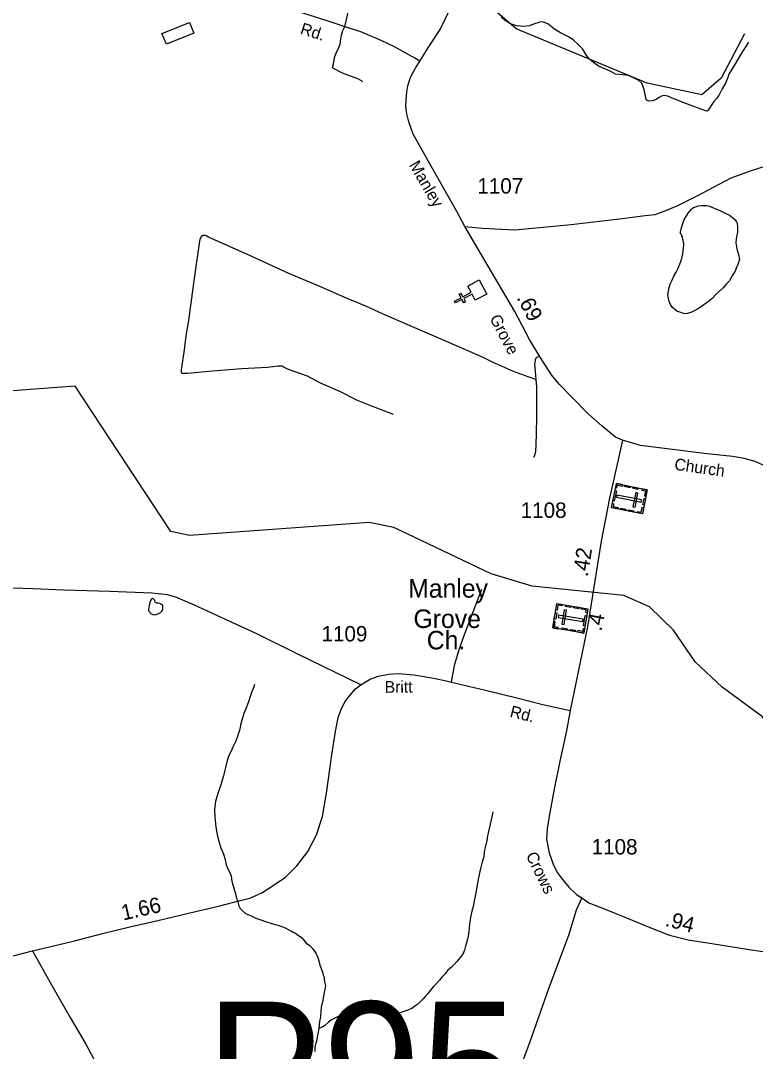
# Model space of a CAD drawing. Extents: x 2206922 to 2357709, y 510027 to 673830.
# Drawn here: x 2230004 to 2235957, y 541278 to 549625 of the extents above; entities that cross this region are included whole.
import ezdxf

# ---------------------------------------------------------------- set-up
doc = ezdxf.new("R2010")
doc.units = 0
for name, color, linetype in [('Exist Cultural Cemetery CELL', 7, 'Continuous'), ('Exist Cultural Cemetery Label', 7, 'Continuous'), ('Exist Cultural Church CELL', 7, 'Continuous'), ('Exist Hydrographic Creek Single Shore', 7, 'Continuous'), ('Exist Hydrographic Misc Water Feature', 7, 'Continuous'), ('Exist Road Non-System Type 51', 7, 'Continuous'), ('Exist Road Secondary Mileage Hundredths English Label', 7, 'Continuous'), ('Exist Road Secondary Structure Pipe Number Label', 7, 'Continuous'), ('Exist Road Secondary Type 51 Attributed', 7, 'Continuous'), ('Exist Road Secondary Type 51 Label', 7, 'Continuous'), ('Exist Road Secondary Type 51 Number Label', 7, 'Continuous')]:
    doc.layers.add(name, color=color, linetype=linetype)

msp = doc.modelspace()

# ---------------------------------------------------------------- linework, layer by layer
at = {"layer": 'Exist Cultural Cemetery CELL'}
for points in [[(2235080.5, 545825.9), (2235041.3, 545630.7), (2234791.6, 545681), (2234830.9, 545876.1)], [(2234830.8, 545817.5), (2234814.1, 545734.4), (2234802.9, 545736.6), (2234819.6, 545819.8)], [(2234824.4, 545843.7), (2234835.7, 545841.4), (2234840, 545863), (2234879.6, 545855), (2234881.8, 545865.9), (2234831, 545876.2)], [(2234899.5, 545862.4), (2234941.9, 545853.8), (2234939.7, 545842.7), (2234897.2, 545851.2)], [(2234965.4, 545849.1), (2235007.8, 545840.6), (2235005.6, 545829.4), (2234963.1, 545837.9)], [(2235005.8, 545799.3), (2234987.5, 545803), (2234964.2, 545687.6), (2234982.5, 545683.9)], [(2235038.1, 545834.5), (2235035.8, 545823.3), (2235067.4, 545817), (2235059.4, 545777.2), (2235070.3, 545775), (2235080.5, 545825.9)], [(2234798.2, 545713.4), (2234809.4, 545711.2), (2234805.1, 545689.6), (2234844.7, 545681.6), (2234842.5, 545670.7), (2234791.6, 545681)], [(2235030.3, 545724.8), (2235034, 545743.1), (2234835.2, 545783.1), (2234831.5, 545764.8)], [(2235065.9, 545753.3), (2235055.7, 545702.5), (2235044.5, 545704.7), (2235054.7, 545755.5)], [(2234864.7, 545677.9), (2234907.2, 545669.3), (2234904.9, 545658.1), (2234862.5, 545666.7)], [(2234929.3, 545664.8), (2234971.8, 545656.3), (2234969.6, 545645.1), (2234927.1, 545653.7)], [(2234998.7, 545639.2), (2235001, 545650.3), (2235032.5, 545644), (2235040.5, 545683.8), (2235051.4, 545681.6), (2235041.2, 545630.7)], [(2234315.7, 544707.8), (2234348.4, 544904.1), (2234599.6, 544862.3), (2234566.9, 544665.9)], [(2234391.2, 544897.1), (2234389.3, 544885.9), (2234357.6, 544891.2), (2234350.9, 544851.2), (2234340, 544853), (2234348.5, 544904.2)], [(2234461.4, 544873.8), (2234418.7, 544880.9), (2234420.6, 544892.2), (2234463.3, 544885)], [(2234526.4, 544863), (2234483.7, 544870.1), (2234485.6, 544881.3), (2234528.3, 544874.2)], [(2234327.9, 544780.8), (2234336.4, 544831.9), (2234347.7, 544830.1), (2234339.2, 544778.9)], [(2234362.5, 544810.5), (2234359.5, 544792.1), (2234559.5, 544758.7), (2234562.6, 544777.2)], [(2234389.6, 544736.8), (2234408, 544733.8), (2234427.3, 544849.9), (2234408.9, 544853)], [(2234594.2, 544829.6), (2234582.8, 544831.5), (2234586.4, 544853.2), (2234546.6, 544859.9), (2234548.4, 544870.8), (2234599.6, 544862.3)], [(2234565, 544724.5), (2234578.9, 544808.2), (2234590.2, 544806.3), (2234576.3, 544722.6)], [(2234358.5, 544700.6), (2234360.3, 544711.8), (2234328.6, 544717.1), (2234335.2, 544757.1), (2234324.2, 544758.9), (2234315.7, 544707.8)], [(2234431.6, 544688.4), (2234388.9, 544695.5), (2234390.7, 544706.8), (2234433.5, 544699.7)], [(2234497.9, 544677.4), (2234455.2, 544684.5), (2234457, 544695.7), (2234499.8, 544688.6)], [(2234572.3, 544698.6), (2234560.9, 544700.4), (2234557.3, 544678.7), (2234517.5, 544685.4), (2234515.6, 544674.4), (2234566.8, 544665.9)]]:
    msp.add_lwpolyline(points, close=True, dxfattribs=at)
at = {"layer": 'Exist Cultural Church CELL'}
msp.add_lwpolyline([(2233688, 547360.7), (2233661, 547410.8), (2233593.9, 547374.9), (2233609, 547346.6), (2233594.9, 547339.1), (2233579.8, 547367.3), (2233526.8, 547338.9), (2233519.2, 547353), (2233572.2, 547381.4), (2233557.1, 547409.6), (2233571.2, 547417.2), (2233586.3, 547389), (2233653.4, 547424.9), (2233626.3, 547475.8), (2233720.1, 547526.1), (2233781.8, 547410.9)], close=True, dxfattribs=at)
at = {"layer": 'Exist Hydrographic Creek Single Shore'}
for points in [[(2235868.2, 549517.9), (2235679.4, 549157.6), (2235522.3, 549023.1), (2235080.2, 549117.2), (2234018.3, 549558.5), (2233808.3, 549739.8)], [(2238109.5, 540472.8), (2238163.4, 541996.9), (2238052.4, 542314), (2237866.5, 542603.1), (2237682.3, 542777.3), (2237121.3, 543106.8), (2236403.4, 543367.2), (2236227.3, 543498.7), (2236107.3, 543855.3), (2236015.3, 543988.4), (2235688.4, 544227.9), (2235469.4, 544432.3), (2235292.2, 544688.5), (2235099.3, 544879.3), (2234890.3, 544968.8), (2234148.3, 545046.1), (2233815.3, 545144.7), (2233028.3, 545521.3), (2232828.3, 545561.4), (2231371.2, 545456.3), (2231221.3, 545488.8), (2230446.2, 546665.6), (2228706.2, 546536.6), (2228754.2, 545669.8)]]:
    msp.add_lwpolyline(points, dxfattribs=at)
at = {"layer": 'Exist Hydrographic Misc Water Feature'}
for points in [[(2232774.8, 549129.6), (2232765.2, 549137.5), (2232735, 549153.4), (2232612.4, 549200.3), (2232544.3, 549233.7), (2232538.2, 549237.5), (2232534.3, 549241.7), (2232532.2, 549245.6), (2232534.3, 549255.5), (2232538.2, 549275.6), (2232549.5, 549333.5), (2232567.1, 549375.8), (2232578.8, 549400), (2232592.5, 549434), (2232594.4, 549458.1), (2232604, 549508.2), (2232615.5, 549546.1), (2232631.5, 549576.2), (2232664.3, 549714.4)], [(2235901.2, 549449.2), (2235839.5, 549354.6), (2235792.6, 549276.2), (2235741.5, 549191.8), (2235733.3, 549163.8), (2235717.7, 549123.6), (2235688.2, 549071.3), (2235660.5, 549019.2), (2235640.6, 548995), (2235619.3, 548971), (2235575.6, 548900.5), (2235565.8, 548892.7), (2235551.6, 548894.4), (2235517.4, 548908.1), (2235429.6, 548939.6), (2235337.1, 548976.7), (2235277.3, 549000.3), (2235246.7, 549013.8), (2235214.7, 549017.4), (2235197.1, 549013.6), (2235177, 549003.3), (2235147.3, 548983), (2235119.6, 548974.6), (2235095.4, 548972.6), (2235081, 548978.4), (2235073, 548986.5), (2235054.6, 549066.3), (2235036.3, 549118.2), (2235012.3, 549140), (2234979.5, 549157.5), (2234929.7, 549179.3), (2234879.9, 549184.7), (2234823.5, 549192.4), (2234785.4, 549214), (2234737.6, 549235.4), (2234687.1, 549257.2), (2234644.9, 549286.7), (2234612.7, 549312.6), (2234592.6, 549340.4), (2234556.3, 549397.8), (2234518, 549435.6), (2234483.3, 549465.6), (2234447.2, 549491.2), (2234378.9, 549524.7), (2234330.5, 549556.3), (2234302.7, 549577.9), (2234276.6, 549597.7), (2234240.7, 549611.2), (2234222.7, 549615.1), (2234202.4, 549610.9), (2234166.3, 549598.9), (2234124.9, 549582.4), (2234081, 549578.1), (2234020.7, 549581.6), (2233972.7, 549599.4), (2233928.4, 549624.7), (2233898.1, 549652.4)], [(2231149, 549520), (2231371.8, 549610.1), (2231406.5, 549522.2), (2231185.3, 549434.6), (2231149, 549520)], [(2235811.4, 547953), (2235813.3, 547910.9), (2235799.9, 547859), (2235798.1, 547824.8), (2235802.6, 547792.9), (2235809, 547767.2), (2235819.2, 547731.2), (2235827.6, 547693.4), (2235815.7, 547649), (2235802, 547621.1), (2235792.6, 547597), (2235768.8, 547558.8), (2235746.8, 547518.7), (2235720.8, 547490.6), (2235695.4, 547462.4), (2235669.7, 547436.3), (2235639.8, 547409.9), (2235606, 547375.7), (2235588.5, 547359.3), (2235558.4, 547337.1), (2235520.9, 547311.1), (2235488.7, 547288.8), (2235465.1, 547276.5), (2235433.3, 547262.3), (2235405.2, 547253.9), (2235387.4, 547251.8), (2235367.1, 547255.6), (2235343.5, 547263.7), (2235321.2, 547273.5), (2235303.1, 547285.1), (2235284.9, 547302.9), (2235270.9, 547320.8), (2235258.4, 547350.7), (2235252.3, 547374.7), (2235248.4, 547404.5), (2235252.1, 547434.8), (2235257.6, 547462.7), (2235267.4, 547490.9), (2235279.1, 547518.6), (2235296.8, 547554.9), (2235314.8, 547589.1), (2235328.3, 547615.1), (2235344.1, 547653.3), (2235357.9, 547689.3), (2235369.1, 547737.4), (2235374.7, 547783.7), (2235376.9, 547801.6), (2235376.7, 547815.4), (2235374.5, 547833.6), (2235370.2, 547853.3), (2235366.3, 547873.3), (2235362.2, 547881.3), (2235360.1, 547885.2), (2235358.3, 547891.2), (2235353.8, 547895.5), (2235350.1, 547903.4), (2235347.8, 547907.4), (2235350.1, 547913.1), (2235357.7, 547949.3), (2235369.3, 547983.2), (2235381.2, 548013.4), (2235395, 548037.7), (2235412.8, 548065.8), (2235438, 548097.7), (2235444.2, 548104.1), (2235456.3, 548112), (2235472.1, 548118.1), (2235496.1, 548124.2), (2235520.3, 548128.7), (2235546.1, 548128.8), (2235564.1, 548126.9), (2235584, 548121.1), (2235623.8, 548105.3), (2235668.1, 548087.8), (2235700.3, 548071.9), (2235746.6, 548048.3), (2235773.1, 548028.5), (2235792.6, 548011), (2235805.1, 547996.9), (2235809.2, 547985), (2235811.4, 547953)], [(2231060.2, 544936.1), (2231058.3, 544930.3), (2231052, 544917.9), (2231050.3, 544908), (2231046.4, 544889.9), (2231042.5, 544873.9), (2231040.7, 544857.9), (2231040.9, 544848.2), (2231044.8, 544841.9), (2231048.9, 544836), (2231053.2, 544830.2), (2231058.9, 544824.4), (2231065.1, 544820.2), (2231074.9, 544816.3), (2231087, 544814.5), (2231101, 544816.4), (2231109, 544818.5), (2231117, 544822.6), (2231127, 544826.7), (2231136.9, 544832.9), (2231148.8, 544842.9), (2231154.7, 544850.9), (2231156.5, 544857.1), (2231156.5, 544868.9), (2231156.5, 544877), (2231156.5, 544885.1), (2231156.5, 544889.2), (2231154.5, 544892.7), (2231146.3, 544896.8), (2231140.1, 544898.9), (2231136.2, 544902.7), (2231132.1, 544904.6), (2231120.3, 544906.8), (2231114.3, 544906.5), (2231110, 544906.7), (2231104.5, 544908.4), (2231098.3, 544912.5), (2231094.2, 544916.4), (2231090.3, 544920.2), (2231090.3, 544926.3), (2231088.1, 544932.3), (2231084, 544936.2), (2231082.1, 544940.1), (2231078.2, 544942.3), (2231074.1, 544944.2), (2231070, 544944.4), (2231064.3, 544940), (2231060.2, 544936.1)], [(2231899, 544249.1), (2231893.7, 544229.3), (2231875.7, 544185), (2231864.2, 544151), (2231852.5, 544116.7), (2231834.9, 544064.6), (2231813.3, 544014.8), (2231795.9, 543960.6), (2231786.3, 543918.6), (2231780.3, 543888.3), (2231770.3, 543856.2), (2231761, 543828.4), (2231741.6, 543780.2), (2231723.7, 543742), (2231705.9, 543704.1), (2231691.9, 543673.8), (2231678, 543633.7), (2231666.5, 543587.6), (2231659.1, 543555.4), (2231649.3, 543519.6), (2231647.6, 543509.7), (2231637.6, 543475.5), (2231626.3, 543437.5), (2231616.1, 543407.4), (2231604.4, 543375.2), (2231592.9, 543339.2), (2231583.3, 543301.3), (2231577.3, 543261.2), (2231574, 543230.9), (2231578.1, 543179.2), (2231580.4, 543147.2), (2231584.9, 543097.1), (2231593.3, 543045.5), (2231601.7, 543011.4), (2231613.8, 542969.4), (2231626.1, 542925.8), (2231646.8, 542874), (2231660.6, 542832.2), (2231669.4, 542789.9), (2231683.7, 542756.2), (2231699.9, 542726.5), (2231710.2, 542698.2), (2231716.3, 542656.3), (2231722.5, 542626.6), (2231728.6, 542610.7), (2231736.8, 542580.6), (2231745.2, 542556.6), (2231751.4, 542527), (2231755.7, 542515), (2231759.4, 542499), (2231765.8, 542483), (2231769.7, 542460.9), (2231784, 542435.2), (2231800.4, 542415.4), (2231826.5, 542395.6), (2231870.7, 542375.9), (2231910.7, 542358.1), (2231948.9, 542344.7), (2231988.6, 542328.9), (2232022.7, 542319.3), (2232055.3, 542307.6), (2232089.1, 542299.6), (2232121.1, 542289.9), (2232146.9, 542278.3), (2232177.3, 542262.3), (2232199, 542252.6), (2232211.3, 542244.7), (2232231.4, 542234.8), (2232253.6, 542219.2), (2232280, 542199.4), (2232299.5, 542179.4), (2232318.2, 542155.6), (2232346.3, 542135.9), (2232370.7, 542107.9), (2232396.9, 542074.4), (2232411.3, 542038.5), (2232421.5, 542002.5), (2232429.5, 541976.5), (2232439.6, 541950.7), (2232449.8, 541920.8), (2232458.2, 541888.7), (2232462.5, 541878.7), (2232464.4, 541859), (2232468.5, 541830.8), (2232473, 541809), (2232467, 541768.9), (2232455.3, 541711.1), (2232449.6, 541677.1), (2232438.5, 541635), (2232436.5, 541602.8), (2232432.6, 541556.8), (2232425.4, 541520.6), (2232421.3, 541468.9), (2232419.5, 541462.7)], [(2233828.8, 543217.2), (2233820.8, 543177.4), (2233813.6, 543141.2), (2233801.7, 543093.2), (2233786.1, 543022.9), (2233780.8, 542985.2), (2233769.3, 542939.1), (2233759.3, 542896.8), (2233757.8, 542852.8), (2233751.9, 542837.1), (2233741.8, 542802.9), (2233736.1, 542781.1), (2233730.8, 542758.8), (2233718.9, 542710.7), (2233711.3, 542670.4), (2233703.7, 542626.6), (2233691.8, 542558.6), (2233680.5, 542510.5), (2233669.3, 542450.5), (2233659.4, 542412.3), (2233651.8, 542376.1), (2233645.9, 542346.2), (2233640.3, 542310.1), (2233636.9, 542276.2), (2233634.6, 542248.1), (2233629.1, 542212), (2233623.5, 542186.2), (2233615.5, 542158.2), (2233609.6, 542130.3), (2233600.4, 542098), (2233590.1, 542069.9), (2233564.3, 542037.8), (2233536.8, 542005.4), (2233515.1, 541979.5), (2233495.2, 541961.4), (2233461.5, 541932.8), (2233443.5, 541906.7), (2233420.1, 541880.7), (2233397.8, 541854.4), (2233370.3, 541824.5), (2233350.4, 541802.4), (2233324.8, 541773.8), (2233303.2, 541745.8), (2233282.9, 541721.7), (2233265.1, 541703.7), (2233247.7, 541685.3), (2233221.6, 541659.2), (2233198, 541644.9), (2233172.2, 541624.9), (2233134.1, 541608.7), (2233108, 541600.5), (2233070.3, 541587.9), (2233042.4, 541585.7), (2233016.4, 541585.5), (2232984.6, 541583), (2232948.5, 541583.2), (2232918.1, 541590.6), (2232886.4, 541596.6), (2232868.3, 541594.5), (2232778.5, 541591.8), (2232736.7, 541595.3), (2232702.2, 541600.9), (2232664.3, 541592.8), (2232644.6, 541584.4), (2232616.7, 541574.4), (2232582.7, 541562.1), (2232554.8, 541549.7), (2232523.2, 541533.4), (2232499.4, 541513.5), (2232467.9, 541487), (2232451.7, 541476.9), (2232419.5, 541462.7)], [(2232419.5, 541462.7), (2232417.6, 541446.7), (2232408.2, 541406.8), (2232400.4, 541360.5), (2232396.7, 541348.5), (2232390.8, 541322.6), (2232387.1, 541306.5), (2232387.3, 541276.5)]]:
    msp.add_lwpolyline(points, dxfattribs=at)
at = {"layer": 'Exist Road Non-System Type 51'}
for points in [[(2233602.3, 547957.9), (2233743.9, 547945.4), (2234006.9, 547930), (2234465.4, 547975.1), (2234877, 548022.1), (2235063, 548046.6), (2235145.7, 548056), (2235230.3, 548086.1), (2235324.2, 548125.5), (2235491.5, 548208.3), (2235762, 548351.2), (2235918, 548407.6), (2236053.3, 548450.8)], [(2234178.7, 546718.1), (2234114.9, 546739.7), (2233997.2, 546784), (2233826.6, 546859.6), (2233745.6, 546898.5), (2233473.5, 547018.4), (2233160.3, 547154.6), (2232935.7, 547249.7), (2232800.7, 547312.3), (2232648.4, 547375), (2232427.1, 547472.2), (2232176.5, 547578.1), (2231841.7, 547730.5), (2231605.2, 547835.3), (2231525.3, 547872), (2231513.5, 547878.5), (2231501.6, 547883.9), (2231495.1, 547885), (2231485.4, 547886.1), (2231481.1, 547885), (2231473.5, 547882.8), (2231465.9, 547873.1), (2231457.3, 547855.8), (2231450.8, 547819.1), (2231441.1, 547744.5), (2231426, 547651.6), (2231408.7, 547517.6), (2231399, 547458.2), (2231364.4, 547196.7), (2231341.8, 547071.4), (2231328.8, 546960.1), (2231305, 546795.8), (2231304, 546784), (2231305, 546775.3), (2231309.4, 546773.2), (2231310.4, 546771), (2231314.8, 546768.8), (2231321.2, 546767.8), (2231328.8, 546768.8), (2231360.1, 546769.9), (2231559.9, 546788.3), (2231796.4, 546806.7), (2232004.8, 546818.5), (2232090.1, 546828.3), (2232108.5, 546829.3), (2232120.4, 546828.3), (2232130.1, 546825), (2232139.8, 546818.5), (2232164.6, 546804.5), (2232216.5, 546785), (2232326.6, 546747.2), (2232430.3, 546693.2), (2232586.9, 546625.1), (2232730.5, 546552.7), (2232824.5, 546513.8), (2233023.2, 546438.2)], [(2234205.6, 546908.2), (2234186.2, 546897.4), (2234180.8, 546893.1), (2234173.3, 546883.4), (2234172.2, 546872.6), (2234167.9, 546840.1), (2234173.3, 546782.9), (2234178.7, 546718.1)], [(2234178.7, 546718.1), (2234182.6, 546658.9), (2234182.6, 546578.5), (2234182.6, 546412.2), (2234181.2, 546285.2), (2234178.4, 546190.8), (2234174.2, 546138.6), (2234169.9, 546111.1), (2234158.7, 546087.1)], [(2232761.3, 544247.6), (2232251, 544493.8), (2231917.2, 544660.2), (2231658.1, 544777), (2231413.1, 544891.9), (2231261.8, 544956.1), (2231195.1, 544974), (2231066.8, 544989.4), (2230726.8, 545002.3), (2230351.6, 545012.1), (2230104.7, 545024.1), (2229766.1, 545035.6), (2229441.5, 545046.5), (2229145.2, 545056.8)], [(2233495, 544268.8), (2233505.3, 544330.4), (2233523.2, 544413.8), (2233556.6, 544531.9), (2233601.5, 544653.8), (2233741.3, 545021.5)], [(2234550.4, 542520.3), (2234505.4, 542422.7), (2234441.6, 542216.1), (2234283.9, 541791.6), (2234130, 541355.9), (2233957.3, 540890.1), (2233702, 540212.1)], [(2230100.2, 542091.1), (2230252.9, 541817.7), (2230405.5, 541553.3), (2230531.2, 541336.4), (2230653.4, 541110.4), (2230715.9, 540966.8), (2230791.6, 540744.7), (2230898.1, 540482.9), (2230967.4, 540284)]]:
    msp.add_lwpolyline(points, dxfattribs=at)
at = {"layer": 'Exist Road Secondary Type 51 Attributed'}
for points in [[(2233239, 549296.6), (2233265.3, 549339.2), (2233291.6, 549383.1), (2233336.1, 549450.4), (2233403.1, 549552.6), (2233479.6, 549709.2), (2233519, 549797.4), (2233632.1, 550111.8), (2233761.7, 550469.9), (2233854.7, 550720.9), (2233894.2, 550819.7), (2233925.2, 550915.5), (2233953.4, 551011.4), (2233983.9, 551134.6), (2234052, 551416.1), (2234131, 551794), (2234246.5, 552304.5), (2234296.4, 552517)], [(2233239, 549296.6), (2233198.9, 549320.4), (2233124.7, 549362.5), (2233034.3, 549411.7), (2232924, 549462.8), (2232759.5, 549533.5), (2232665.3, 549564.6), (2232478.8, 549627.1), (2231929.7, 549802.6), (2231502.7, 549945), (2230502.5, 550264.7), (2229623, 550561.2), (2229298.8, 550665.9)], [(2234881.6, 546226.3), (2234824.3, 546251.5), (2234715.4, 546340.3), (2234598.9, 546443.7), (2234471.1, 546576.3), (2234368.1, 546679.9), (2234303.8, 546757.7), (2234212.4, 546898.5), (2234127.1, 547043.8), (2234007.4, 547270.7), (2233602.3, 547957.9), (2233537.2, 548079.5), (2233340.5, 548426.7), (2233185.1, 548706.2), (2233148.8, 548805.2), (2233133.8, 548869.1), (2233125, 548929.3), (2233126.3, 548980.7), (2233133.8, 549047.1), (2233141.3, 549097.3), (2233150.1, 549123.6), (2233166.3, 549172.5), (2233202.7, 549238.9), (2233239, 549296.6)], [(2234881.6, 546226.3), (2234836.2, 546032.6), (2234775.7, 545756.8), (2234708, 545410.9), (2234597.9, 544716.7), (2234522.9, 544364.3), (2234457.5, 544037.9)], [(2236084.4, 545994.9), (2235953.8, 546054.5), (2235865.2, 546078.7), (2235771.7, 546094.8), (2235541.2, 546119), (2235262.5, 546153.9), (2235024.8, 546184.1), (2234881.6, 546226.3)], [(2229783.4, 542011.5), (2230100.2, 542091.1), (2230295.2, 542139.5), (2230440.7, 542174.2), (2230668.5, 542231.9), (2230889.8, 542285.8), (2231114.9, 542336.9), (2231363.1, 542397.5), (2231619, 542456.2), (2231782.5, 542500.5), (2231861.4, 542519.7), (2231959.6, 542561.1), (2232066.2, 542631.1), (2232150.1, 542690.1), (2232240.5, 542780.6), (2232330.9, 542898), (2232400.2, 543032.8), (2232450.2, 543181), (2232482.9, 543367.8), (2232525.5, 543680.3), (2232555.9, 543868.5), (2232577.2, 543981.9), (2232600.3, 544045.4), (2232631.7, 544109), (2232670.2, 544160.3), (2232717.7, 544214.2), (2232761.3, 544247.6), (2232836.4, 544292.5), (2232900, 544317), (2232983.2, 544333.6), (2233062.7, 544338.7), (2233191, 544327.2), (2233256.4, 544316.9), (2233348.8, 544300.2), (2233442.1, 544281.5), (2233495, 544268.8), (2233770.7, 544204.3), (2234024.9, 544140.4), (2234235.4, 544088), (2234457.5, 544037.9)], [(2234457.5, 544037.9), (2234427, 543873.8), (2234373.6, 543628.2), (2234326.9, 543402.5), (2234285, 543181.6), (2234268.8, 543081.6), (2234265.6, 542996.1), (2234286.6, 542886.5), (2234301.1, 542839.7), (2234318.8, 542792.9), (2234349.4, 542733.3), (2234383.3, 542683.3), (2234446.1, 542609.1), (2234507.4, 542549.4), (2234550.4, 542520.3), (2234607.3, 542481.7), (2234739.5, 542428.5), (2234911.9, 542359.1), (2235110.1, 542278.5), (2235260, 542220.5), (2235411.5, 542181.8), (2235604.9, 542151.1), (2235922.4, 542099.5), (2236131.9, 542072.1)]]:
    msp.add_lwpolyline(points, dxfattribs=at)

# ---------------------------------------------------------------- texts
at = {"layer": 'Exist Cultural Cemetery Label'}
for s, p in [('Manley', (2233143.6, 544952.4)), ('Grove', (2233187.1, 544706.7)), ('Ch.', (2233294.5, 544533.3))]:
    msp.add_text(s, height=150, dxfattribs=at).set_placement(p)
at = {"layer": 'Exist Road Secondary Mileage Hundredths English Label'}
for s, rotation, p in [('.69', 297.81366, (2234019.8, 547381.2)), ('.42', 80.98868, (2234598.1, 545117)), ('.4', 78.6278, (2234709.1, 544675.8)), ('1.66', 12.76867, (2230834.4, 542337.4)), ('.94', 345.6697, (2235219.4, 542295.4))]:
    msp.add_text(s, height=125, rotation=rotation, dxfattribs=at).set_placement(p)
at = {"layer": 'Exist Road Secondary Structure Pipe Number Label'}
msp.add_text('P95', height=1066.27, dxfattribs=at).set_placement((2231501.5, 540614.1))
at = {"layer": 'Exist Road Secondary Type 51 Label'}
for s, rotation, p in [('Rd.', 342.27524, (2232262.9, 549520)), ('Manley', 300.25977, (2233147.8, 548456.4)), ('Grove', 297.81366, (2233800.7, 547214.9)), ('Church', 351.94679, (2235296.4, 545988.4)), ('Britt', 0.39539, (2232954.2, 544181.5)), ('Rd.', 345.88931, (2233962.3, 543988.8)), ('Crows', 296.10832, (2234095.2, 542866.2))]:
    msp.add_text(s, height=95, rotation=rotation, dxfattribs=at).set_placement(p)
at = {"layer": 'Exist Road Secondary Type 51 Number Label'}
for s, p in [('1107', (2233704.1, 548224.3)), ('1108', (2234055.3, 545598.2)), ('1109', (2232441.6, 544597.5)), ('1108', (2234630.1, 542872.5))]:
    msp.add_text(s, height=125, dxfattribs=at).set_placement(p)

doc.saveas('drawing.dxf')
